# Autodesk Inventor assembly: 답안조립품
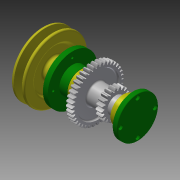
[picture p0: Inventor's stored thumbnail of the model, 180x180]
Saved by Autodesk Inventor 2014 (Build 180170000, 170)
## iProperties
Created: 2016-10
Part Number: 답안조립품
Document SubType Name: Assembly
Designer: USER
Author: USER
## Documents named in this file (13)
- C:\Users\USER\Desktop\461008V1018\답안조립품.iam
- C:\Users\USER\Desktop\461008V1018\V-벨트풀리.ipt
- C:\Users\USER\Desktop\461008V1018\뒤커버.ipt
- C:\Users\USER\Desktop\461008V1018\멈춤나사 - M4x10.ipt
- C:\Users\USER\Desktop\461008V1018\본체.ipt
- C:\Users\USER\Desktop\461008V1018\부시.ipt
- C:\Users\USER\Desktop\461008V1018\스퍼기어.ipt
- C:\Users\USER\Desktop\461008V1018\앞커버.ipt
- C:\Users\USER\Desktop\461008V1018\오일씰 28 40 8.ipt
- C:\Users\USER\Desktop\461008V1018\축.ipt
- C:\Users\USER\Desktop\461008V1018\키 - 5 x 5 x 18.ipt
- C:\Users\USER\Desktop\461008V1018\키 - 6 x 6 x 22.ipt
- C:\Users\USER\Desktop\461008V1018\베어링 6203.ipt
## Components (1 placed, 1 different names)
1. V-벨트풀리:1
